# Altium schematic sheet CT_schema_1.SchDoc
size 729 x 599 mm
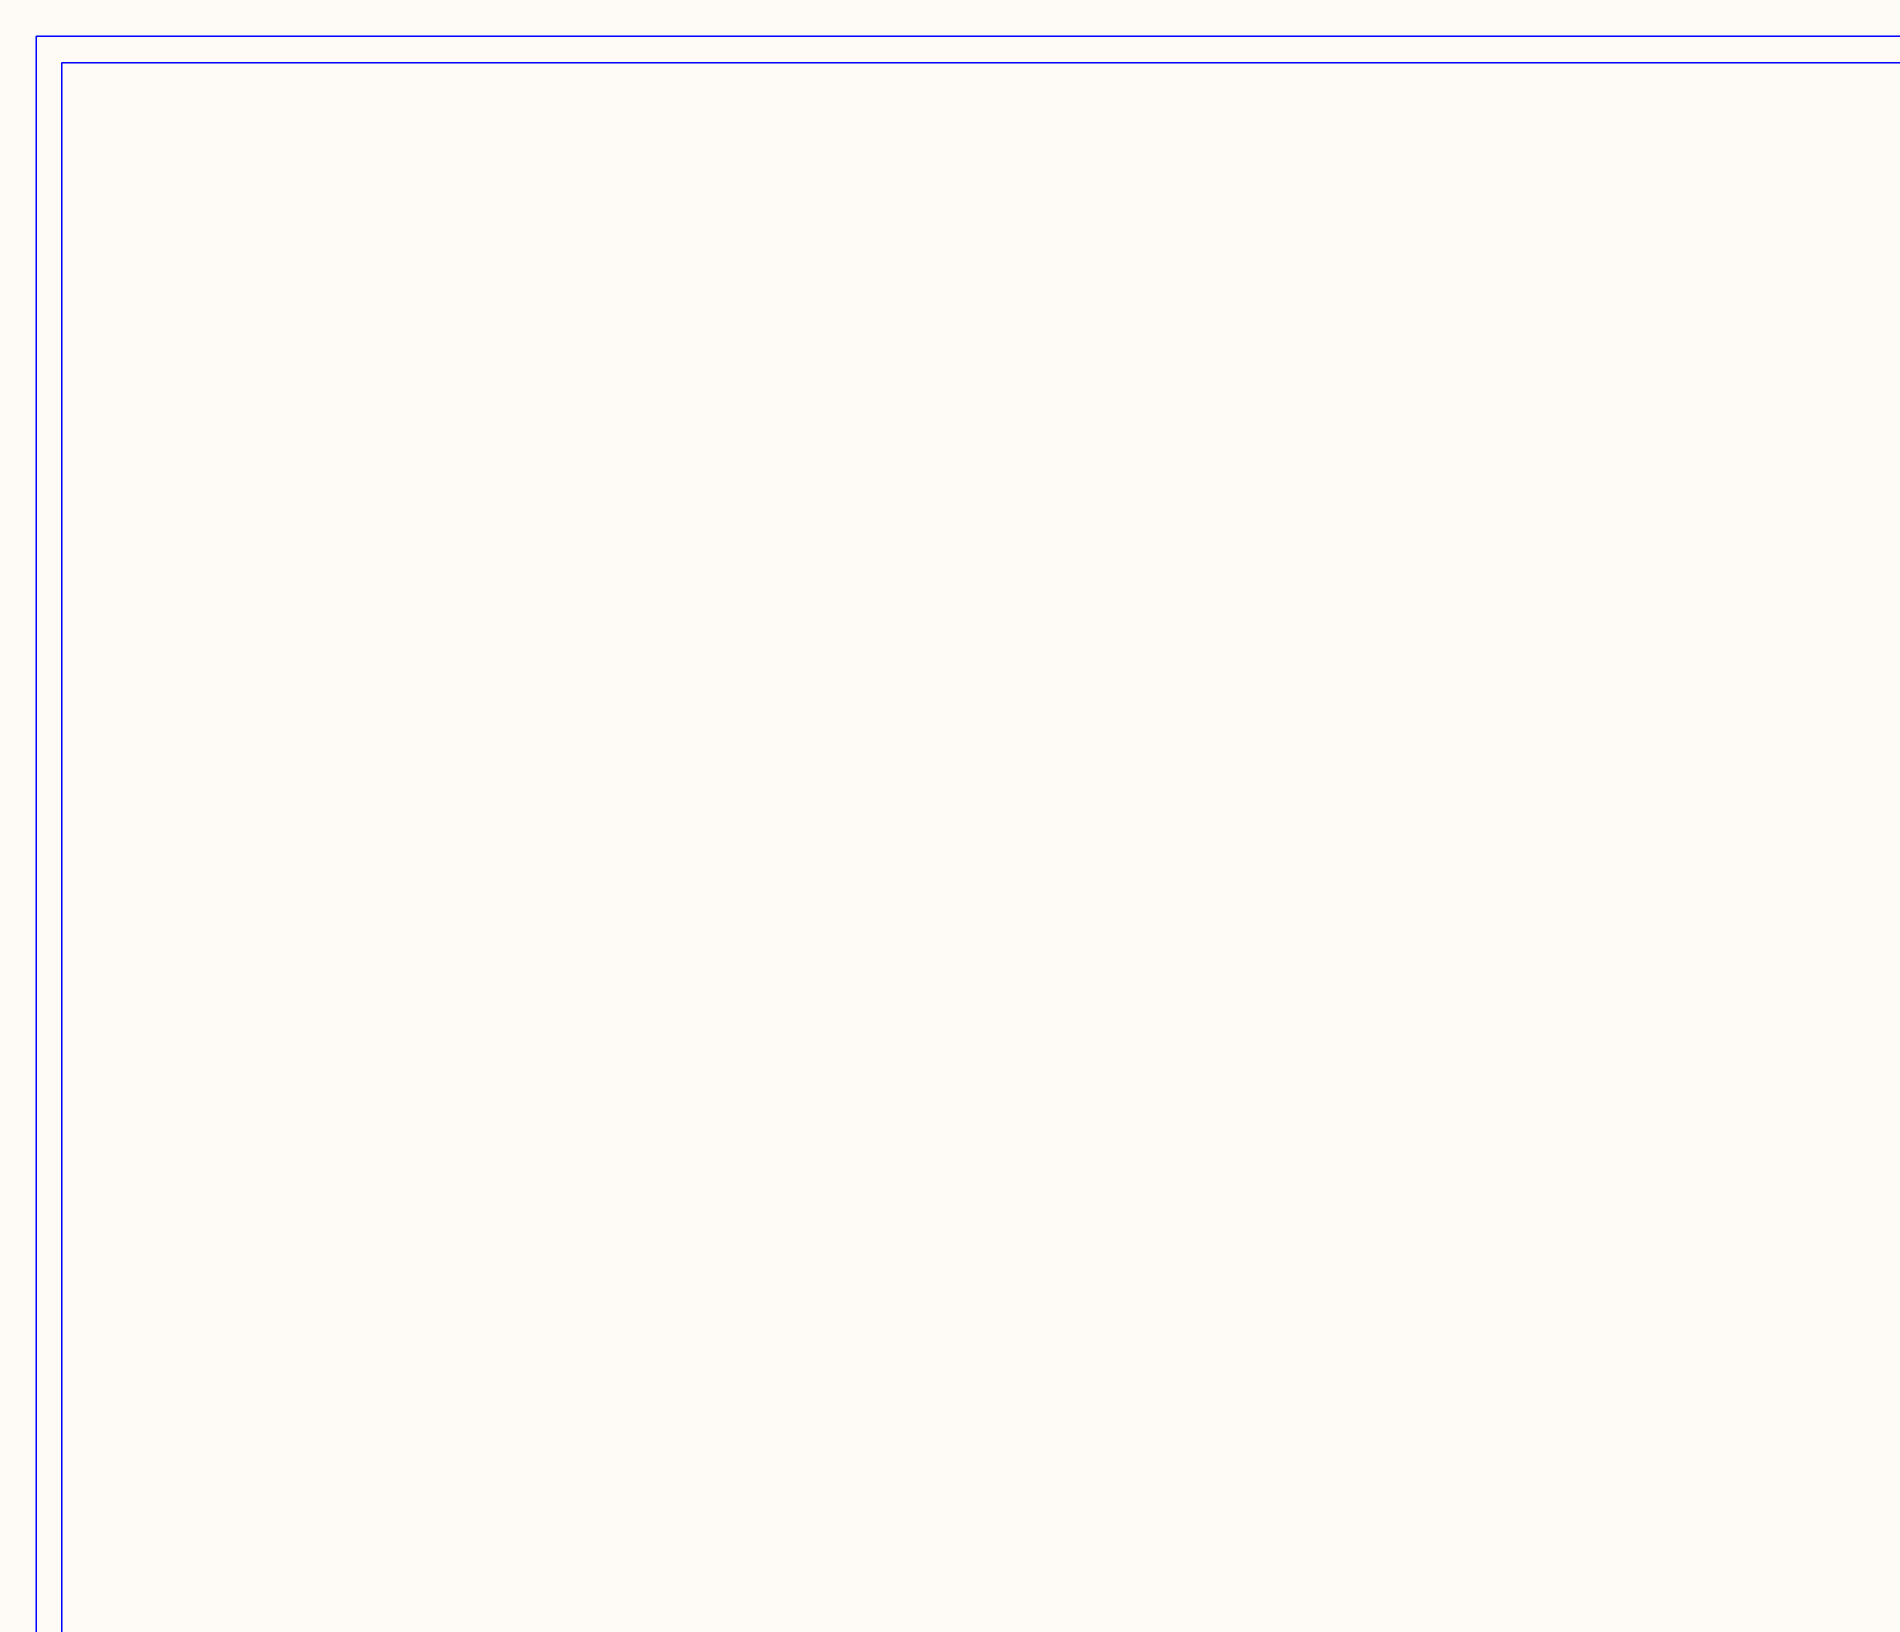
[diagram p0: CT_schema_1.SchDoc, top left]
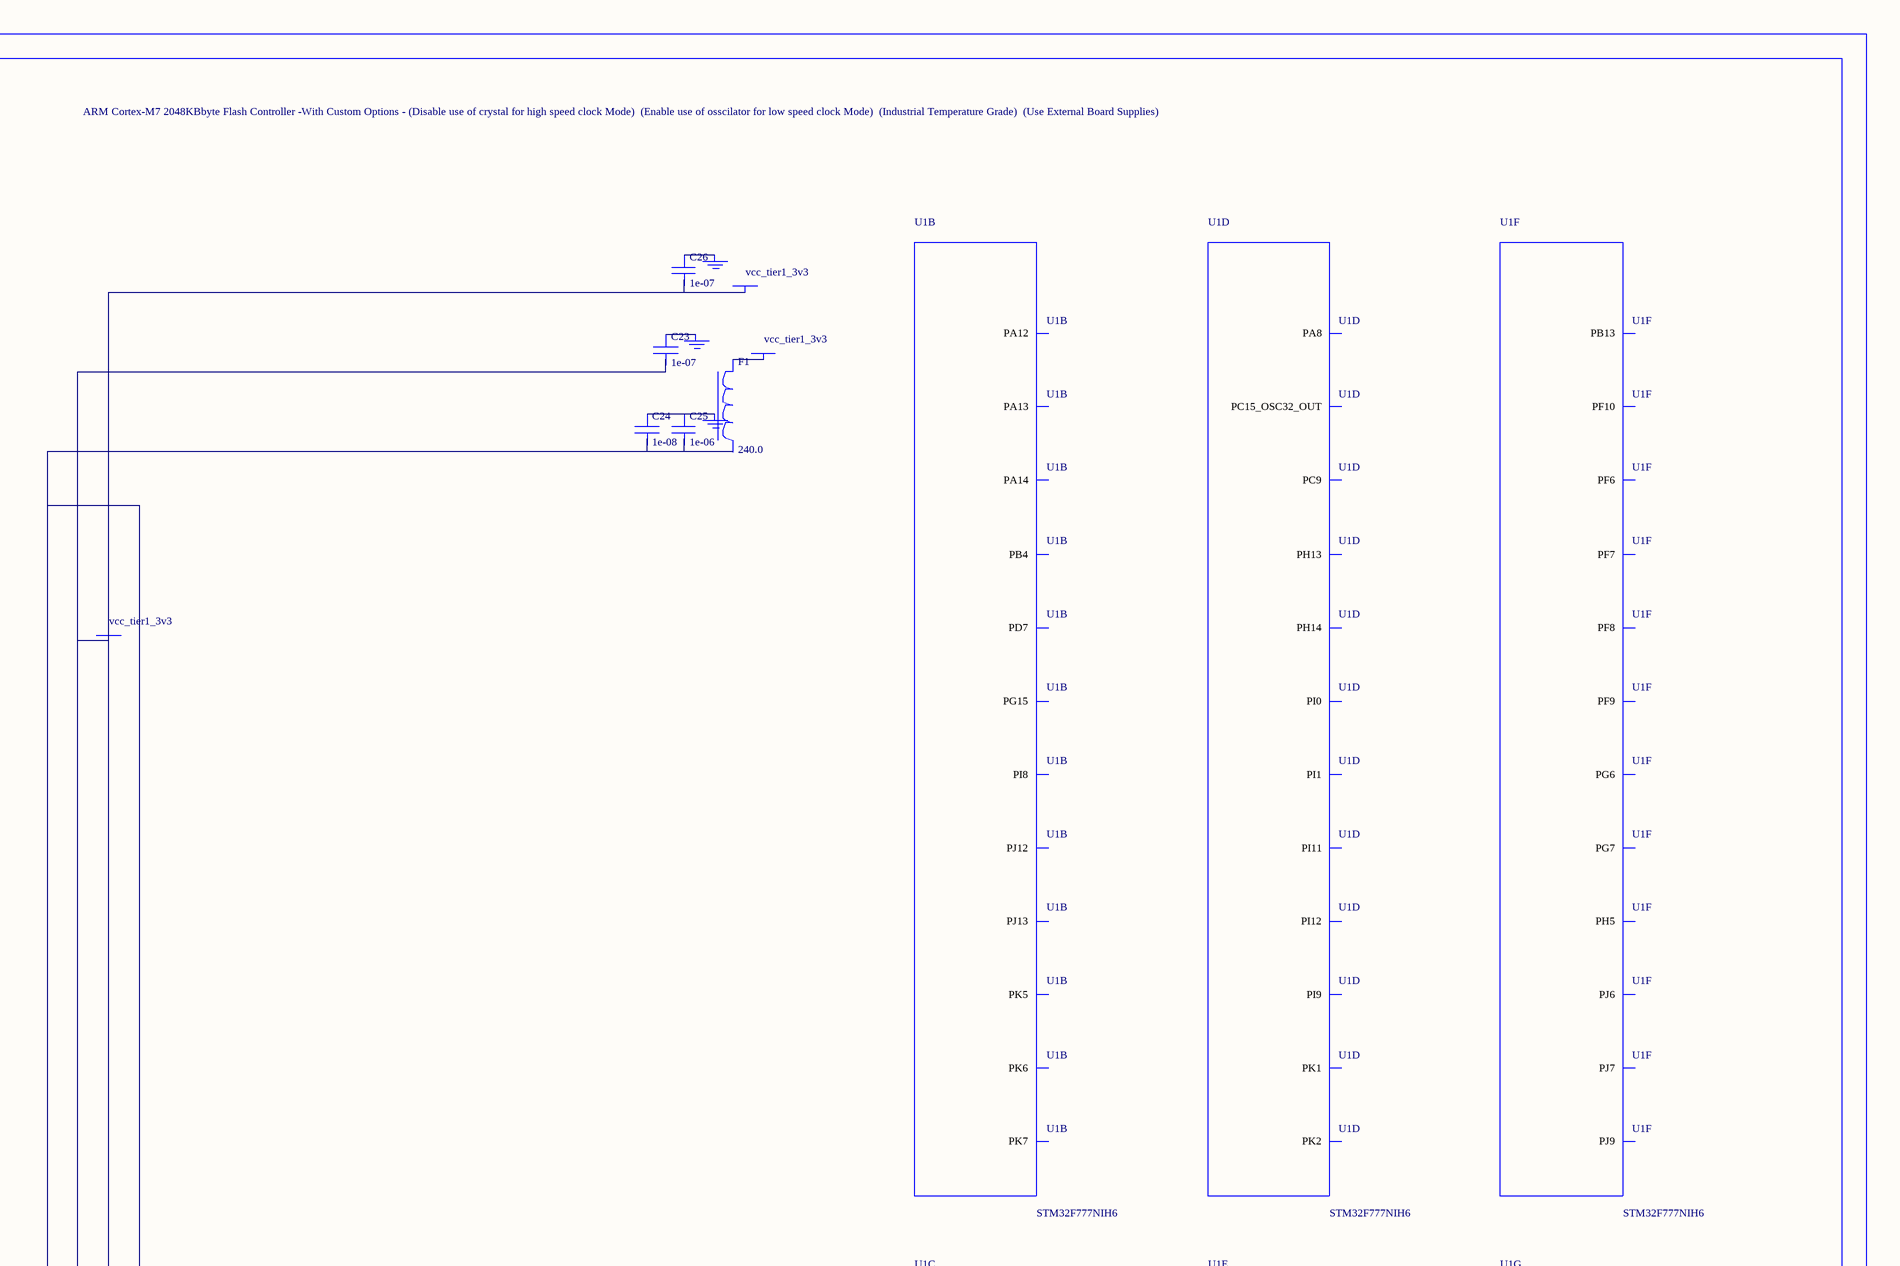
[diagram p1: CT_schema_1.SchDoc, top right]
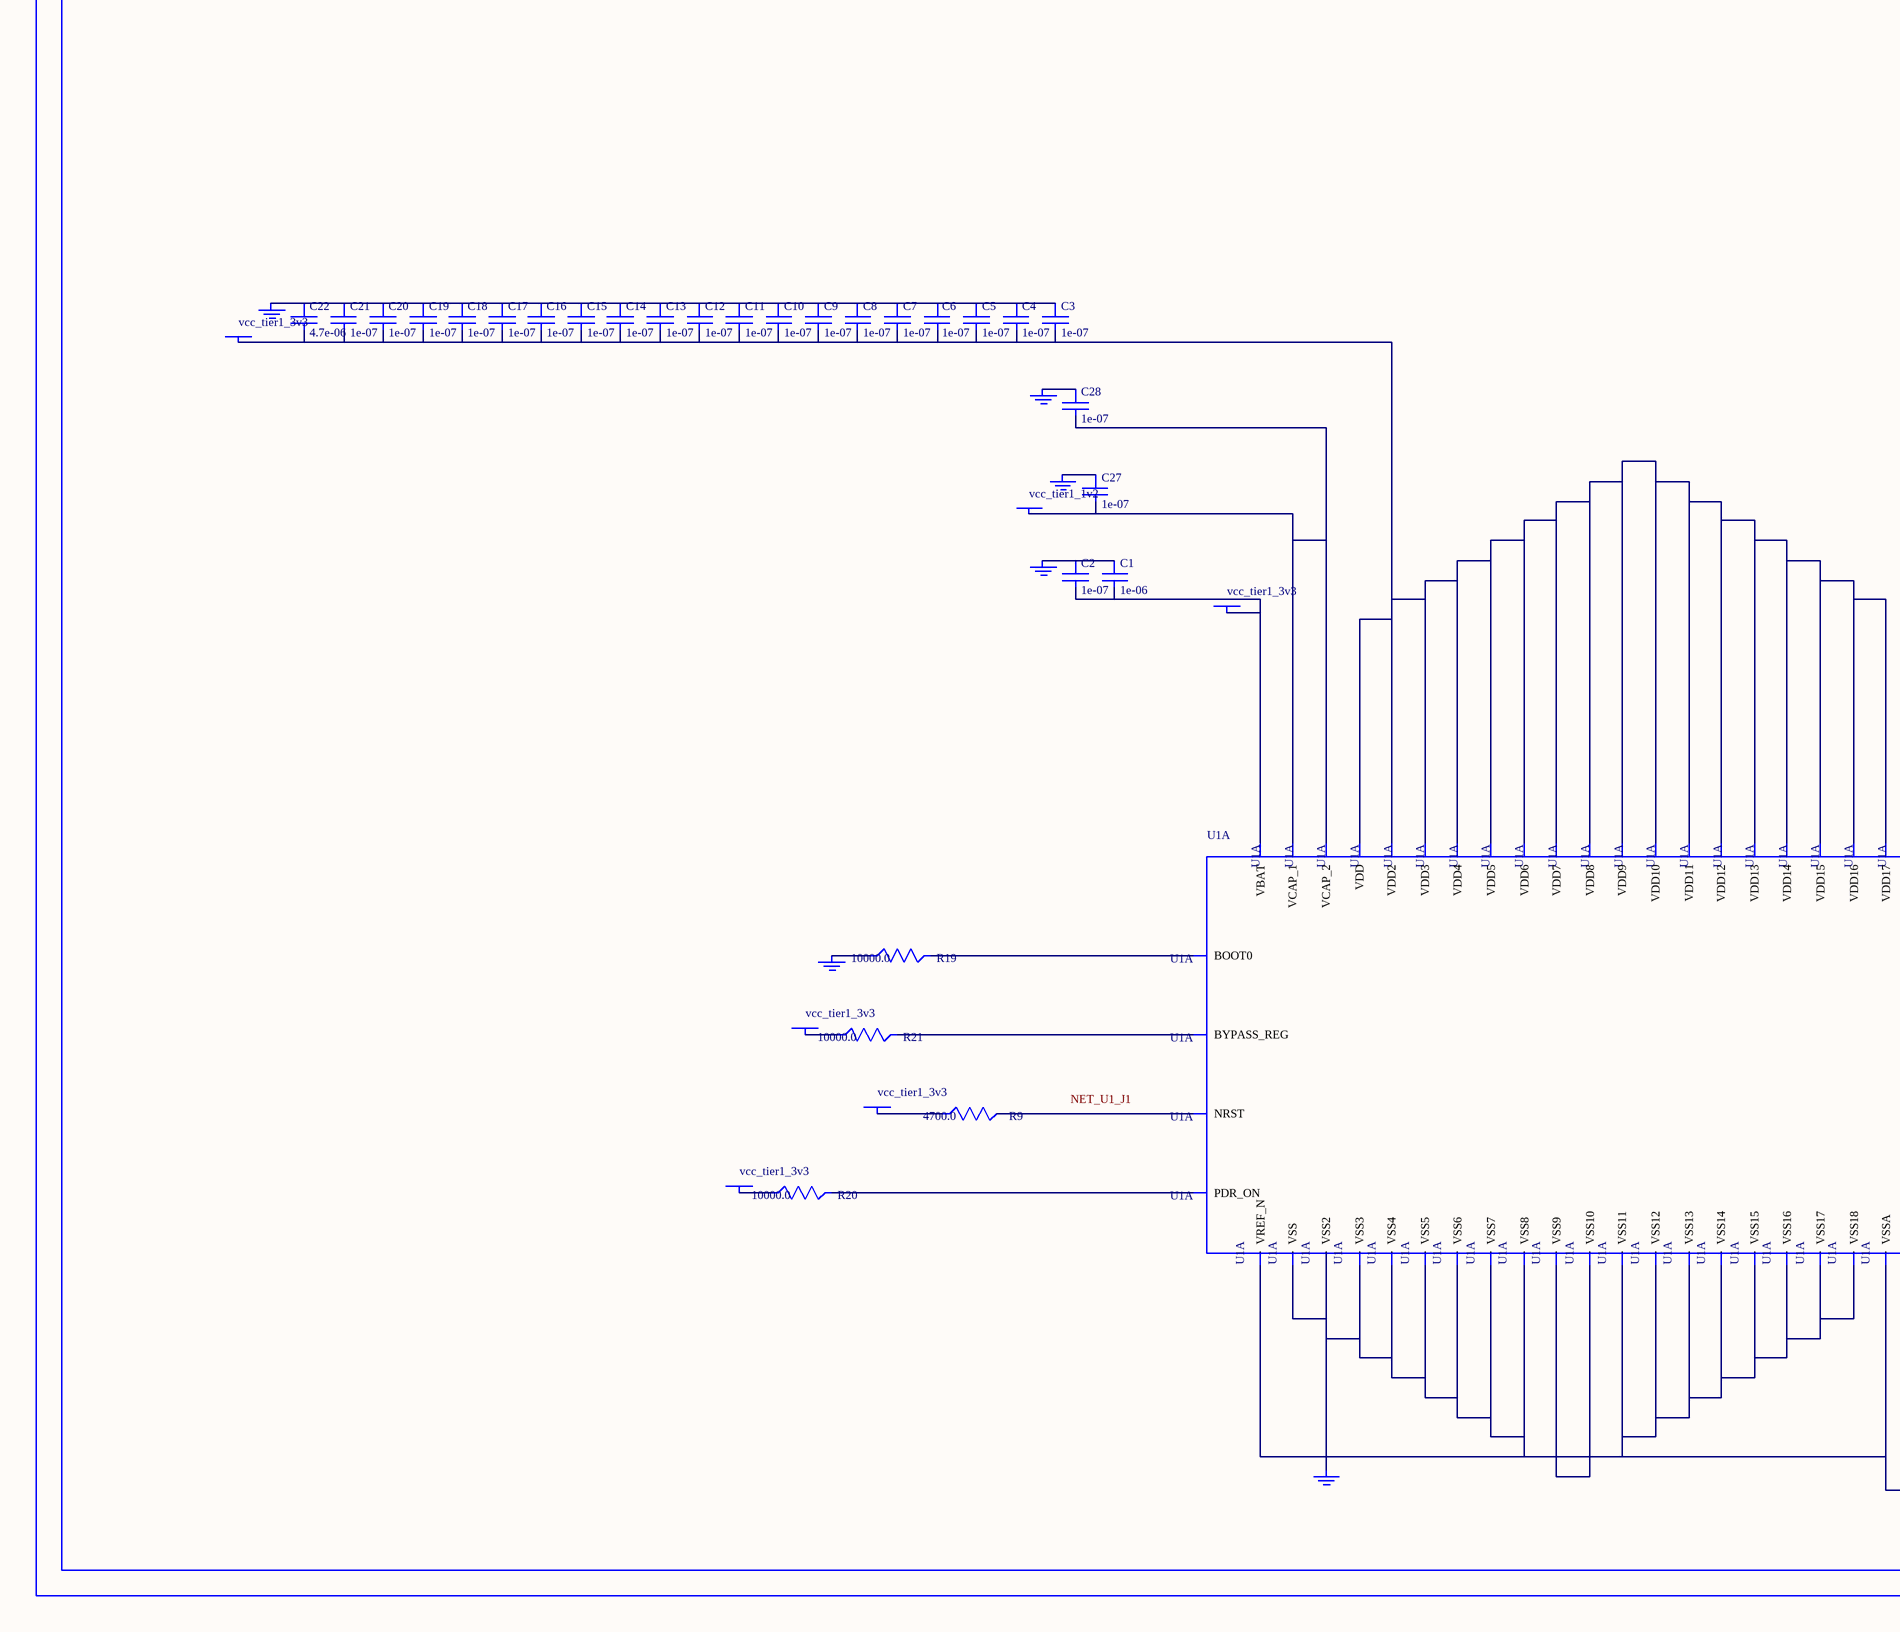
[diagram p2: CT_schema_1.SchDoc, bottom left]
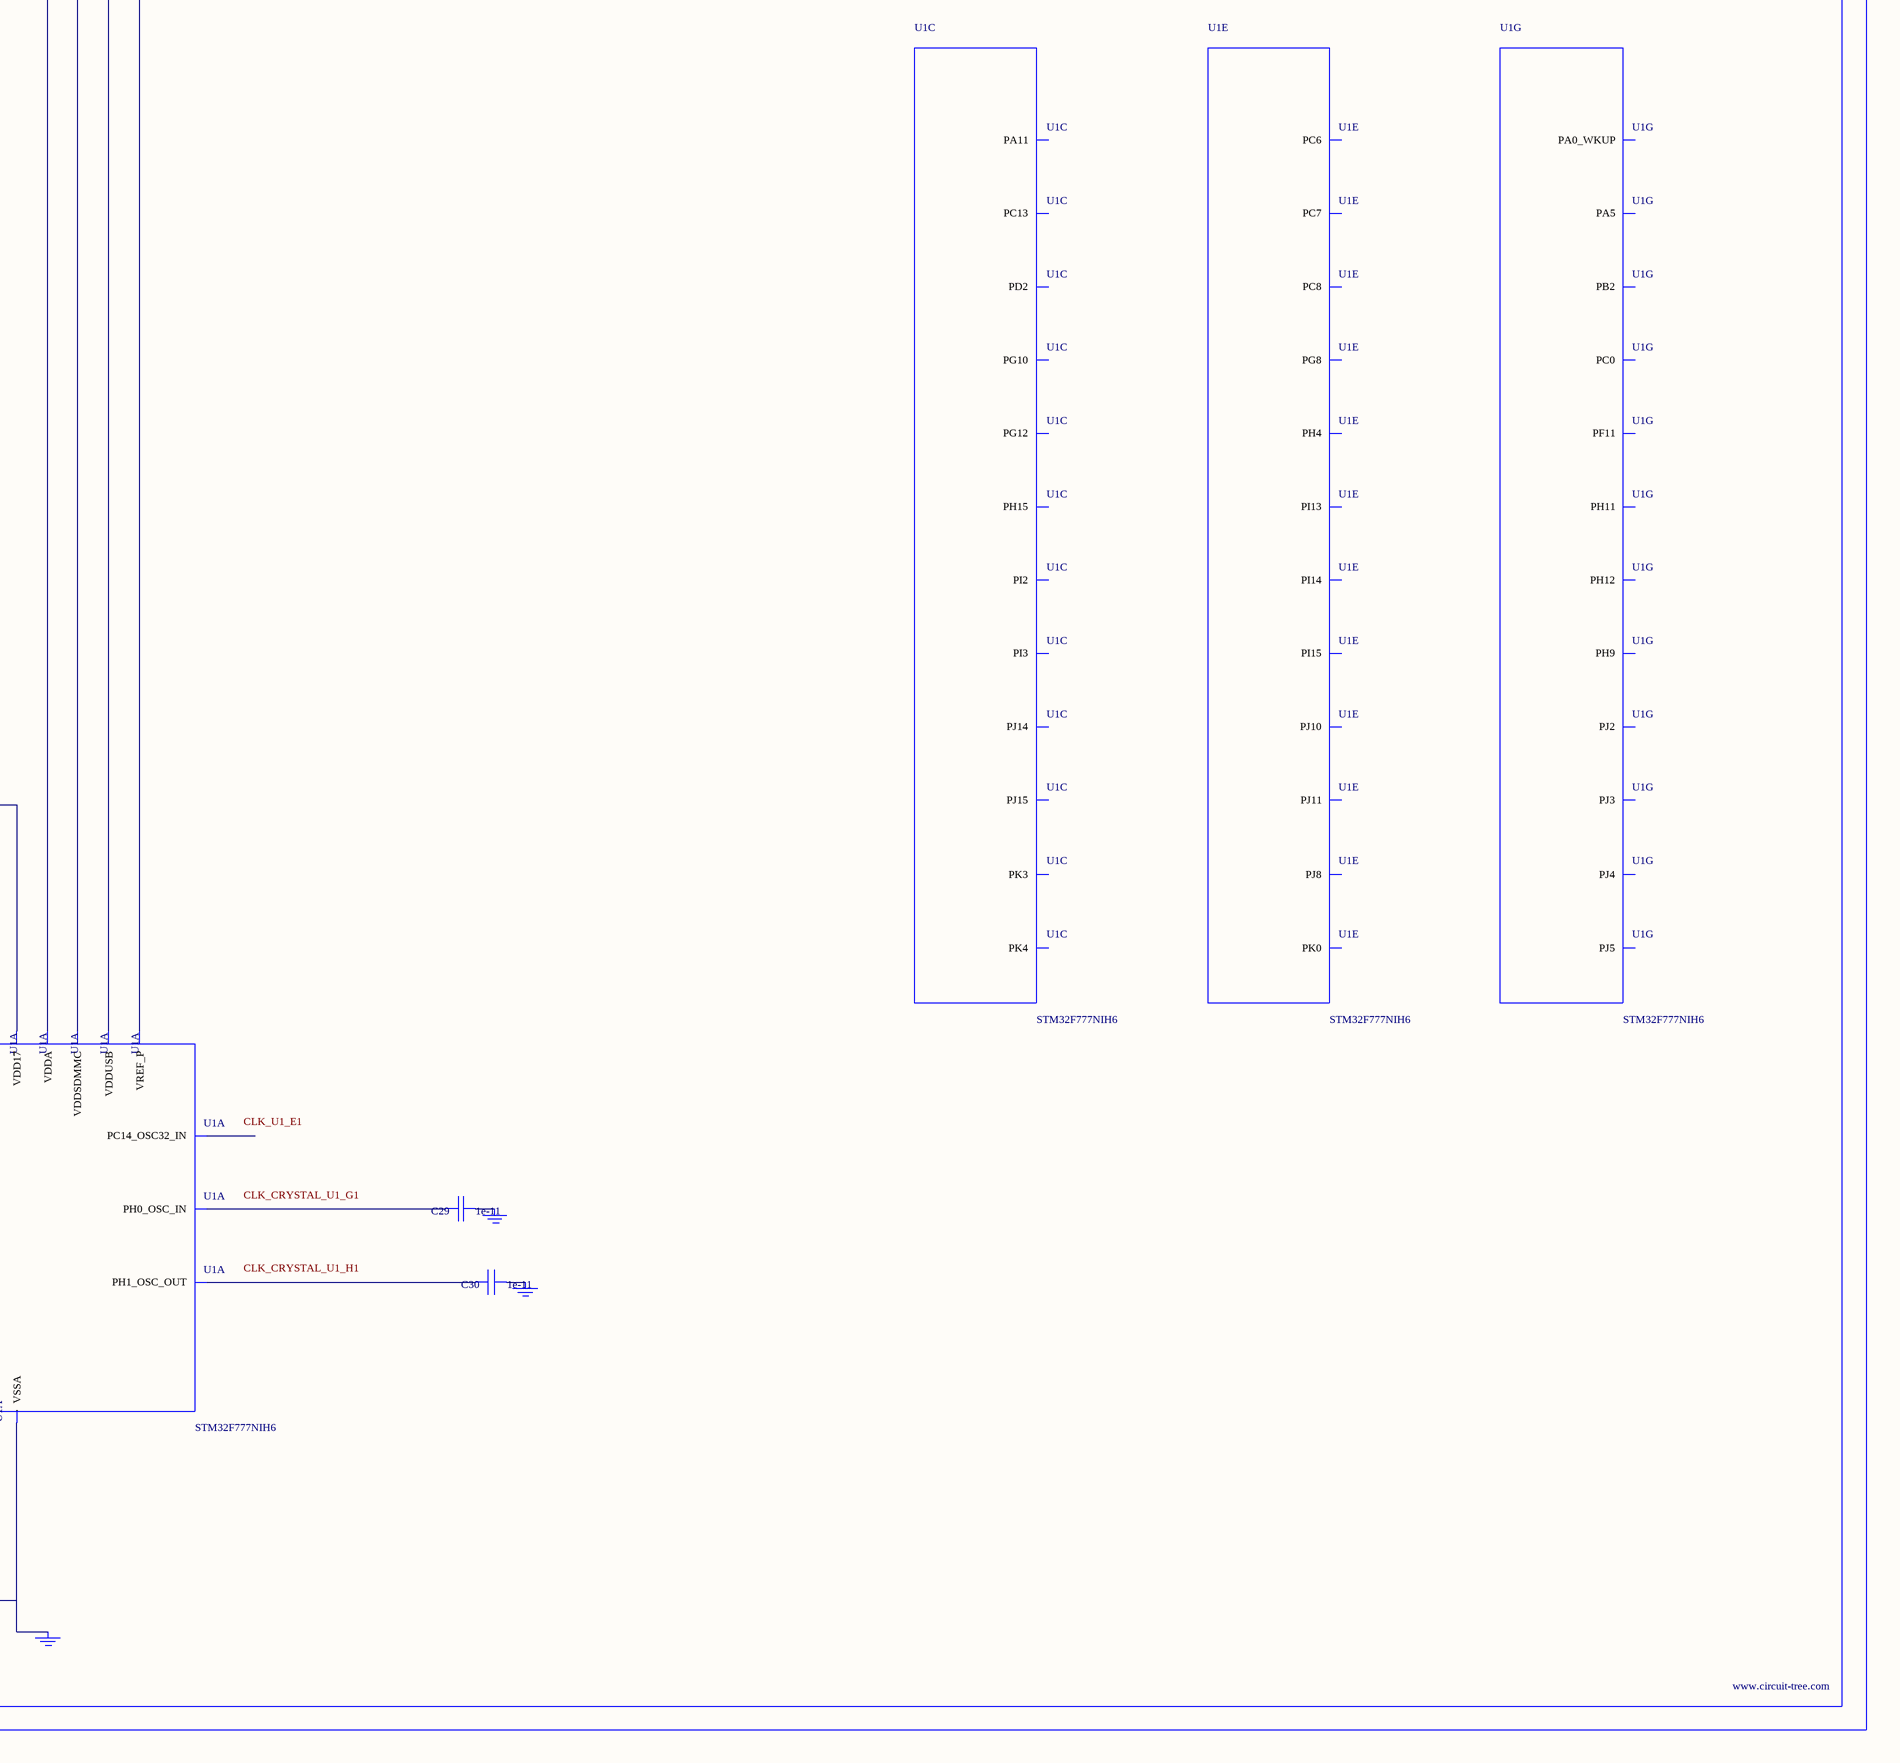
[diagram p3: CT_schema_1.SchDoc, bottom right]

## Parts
BORDER0  (no value)
C1  1e-06  [C0603]
C2  1e-07  [C0603]
C3  1e-07  [C0603]
C4  1e-07  [C0603]
C5  1e-07  [C0603]
C6  1e-07  [C0603]
C7  1e-07  [C0603]
C8  1e-07  [C0603]
C9  1e-07  [C0603]
C10  1e-07  [C0603]
C11  1e-07  [C0603]
C12  1e-07  [C0603]
C13  1e-07  [C0603]
C14  1e-07  [C0603]
C15  1e-07  [C0603]
C16  1e-07  [C0603]
C17  1e-07  [C0603]
C18  1e-07  [C0603]
C19  1e-07  [C0603]
C20  1e-07  [C0603]
C21  1e-07  [C0603]
C22  4.7e-06  [C0603]
C23  1e-07  [C0603]
C24  1e-08  [C0603]
C25  1e-06  [C0603]
C26  1e-07  [C0603]
C27  1e-07  [C0603]
C28  1e-07  [C0603]
C29  1e-11  [C0402]
C30  1e-11  [C0402]
F1  240.0  [L0603]
GND_INSTANCE_0_0  (no value)
GND_INSTANCE_0_1  (no value)
GND_INSTANCE_0_2  (no value)
GND_INSTANCE_0_3  (no value)
GND_INSTANCE_0_4  (no value)
GND_INSTANCE_0_5  (no value)
GND_INSTANCE_0_6  (no value)
GND_INSTANCE_0_7  (no value)
GND_INSTANCE_0_8  (no value)
GND_INSTANCE_0_9  (no value)
GND_INSTANCE_0_10  (no value)
GND_INSTANCE_0_11  (no value)
POWER_INSTANCE_0_0  vcc_tier1_3v3
POWER_INSTANCE_0_1  vcc_tier1_3v3
POWER_INSTANCE_0_2  vcc_tier1_3v3
POWER_INSTANCE_0_3  vcc_tier1_3v3
POWER_INSTANCE_0_4  vcc_tier1_3v3
POWER_INSTANCE_0_5  vcc_tier1_3v3
POWER_INSTANCE_0_6  vcc_tier1_3v3
POWER_INSTANCE_0_7  vcc_tier1_1v2
POWER_INSTANCE_0_8  vcc_tier1_3v3
R9  4700.0  [R0603]
R19  10000.0  [R0603]
R20  10000.0  [R0603]
R21  10000.0  [R0603]
U1  STM32F777NIH6  [TFBGA216]  (parts A,B,C,D,E,F,G of 15)

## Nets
NetC1_1: C1.1 C2.1 GND_INSTANCE_0_0.0(GND)
NetC1_2: C1.2 C2.2 POWER_INSTANCE_0_0.0(PWR) U1.C1(VBAT)
NetC3_1: C3.1 C4.1 C5.1 C6.1 C7.1 C8.1 C9.1 C10.1 C11.1 C12.1 C13.1 C14.1 C15.1 C16.1 C17.1 C18.1 C19.1 C20.1 C21.1 C22.1 GND_INSTANCE_0_2.0(GND)
NetC3_2: C3.2 C4.2 C5.2 C6.2 C7.2 C8.2 C9.2 C10.2 C11.2 C12.2 C13.2 C14.2 C15.2 C16.2 C17.2 C18.2 C19.2 C20.2 C21.2 C22.2 POWER_INSTANCE_0_2.0(PWR) U1.E7(VDD2) U1.E8(VDD3) U1.E10(VDD) U1.F4(VDD5) U1.F5(VDD6) U1.F11(VDD4) U1.G5(VDD7) U1.H5(VDD9) U1.H11(VDD8) U1.J5(VDD11) U1.J11(VDD10) U1.K5(VDD13) U1.K11(VDD12) U1.L7(VDD15) U1.L8(VDD16) U1.L9(VDD17) U1.L10(VDD14)
NetC23_1: C23.1 GND_INSTANCE_0_4.0(GND)
NetC23_2: C23.2 C26.2 POWER_INSTANCE_0_3.0(PWR) POWER_INSTANCE_0_5.0(PWR) U1.E9(VDDSDMMC) U1.G11(VDDUSB)
NetC24_1: C24.1 C25.1 GND_INSTANCE_0_1.0(GND)
NetC24_2: C24.2 C25.2 U1.P1(VREF_P) U1.R1(VDDA)
NetC26_1: C26.1 GND_INSTANCE_0_5.0(GND)
NetC27_1: C27.1 GND_INSTANCE_0_6.0(GND)
NetC27_2: C27.2 C28.2 POWER_INSTANCE_0_7.0(PWR) U1.E11(VCAP_2) U1.L11(VCAP_1)
NetC28_1: C28.1 GND_INSTANCE_0_7.0(GND)
NetC29_1: C29.1 GND_INSTANCE_0_8.0(GND)
NetC29_2: C29.2 U1.G1(PH0_OSC_IN)
NetC30_1: C30.1 GND_INSTANCE_0_9.0(GND)
NetC30_2: C30.2 U1.H1(PH1_OSC_OUT)
NetF1_1: F1.1 POWER_INSTANCE_0_1.0(PWR)
NetGND_INSTANCE_0_3_0: GND_INSTANCE_0_3.0(GND) R19.1
NetGND_INSTANCE_0_10_0: GND_INSTANCE_0_10.0(GND) GND_INSTANCE_0_11.0(GND) U1.F2(VSS2) U1.F6(VSS3) U1.F7(VSS4) U1.F8(VSS5) U1.F9(VSS6) U1.F10(VSS) U1.G6(VSS8) U1.G10(VSS7) U1.H6(VSS10) U1.H10(VSS9) U1.J6(VSS12) U1.J10(VSS11) U1.K6(VSS14) U1.K7(VSS15) U1.K8(VSS16) U1.K9(VSS17) U1.K10(VSS13) U1.L6(VSS18) U1.M1(VSSA) U1.N1(VREF_N)
NetPOWER_INSTANCE_0_4_0: POWER_INSTANCE_0_4.0(PWR) R20.1
NetPOWER_INSTANCE_0_6_0: POWER_INSTANCE_0_6.0(PWR) R21.1
NetPOWER_INSTANCE_0_8_0: POWER_INSTANCE_0_8.0(PWR) R9.1
NetR9_2: R9.2 U1.J1(NRST)
NetR19_2: R19.2 U1.E6(BOOT0)
NetR20_2: R20.2 U1.E5(PDR_ON)
NetR21_2: R21.2 U1.L5(BYPASS_REG)

Not connected (* = marked no-connect by the designer): F1 2; U1 A9(PB4) A11(PD7) A14(PA14) A15(PA13) B7(PG15) B9(PJ13) B10(PJ12) B15(PA12) C2(PI8) C4(PK7) C5(PK6) C6(PK5) C7(PG12) C8(PG10) C9(PJ14) C13(PI3) C14(PI2) C15(PA11) D1(PC13) D7(PK4) D8(PK3) D10(PJ15) D12(PD2) D13(PH15) D14(PI1) E1(PC14_OSC32_IN) E3(PI12) E4(PI9) E12(PH13) E13(PH14) E14(PI0) F1(PC15_OSC32_OUT) F3(PI11) F12(PK1) F13(PK2) F14(PC9) F15(PA8) G3(PI13) G4(PI15) G12(PJ11) G13(PK0) G14(PC8) G15(PC7) H3(PI14) H4(PH4) H12(PJ8) H13(PJ10) H14(PG8) H15(PC6) J3(PH5) J12(PJ7) J13(PJ9) J14(PG7) J15(PG6) K1(PF7) K2(PF6) K12(PJ6) K14(PB13) L1(PF10) L2(PF9) L3(PF8) M2(PC0) M5(PB2) M9(PJ4) M14(PJ5) M15(PH12) N3(PA0_WKUP) N8(PJ3) N14(PH9) N15(PH11) P4(PA5) P7(PJ2) P8(PF11)

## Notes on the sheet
- Labels drawn without touching a wire or pin: CLK_CRYSTAL_U1_G1, CLK_CRYSTAL_U1_H1, CLK_U1_E1, NET_U1_J1

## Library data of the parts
BORDER0 = BORDER_PAGE0
C1 C25 = C0603C105K3RACTU
C2-C21 C23 C26-C28 = 06035C104K4Z2A
C22 = GRM188R6YA475KE15D
C24 = 06035C103K4Z2A
C29 C30 = C0402C100K3GACTU
F1 = Z0603C241ASMST
GND_INSTANCE_0_0-GND_INSTANCE_0_11 = GND
POWER_INSTANCE_0_0-POWER_INSTANCE_0_8 = PWR
R9 = RC0603JR-074K7L
R19-R21 = RC0603JR-0710KL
